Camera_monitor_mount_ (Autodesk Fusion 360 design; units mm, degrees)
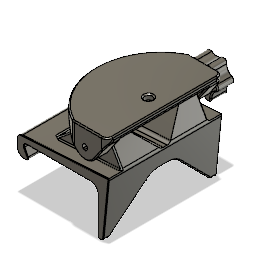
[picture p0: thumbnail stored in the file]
sketch "Sketch1" plane through (0, 0, 0) normal (0, 0, 1) x axis (1, 0, 0)
  line L1 (60, 0) -> (0, 0)
  line L2 (60, 40) -> (60, 0)
  line L3 (0, 40) -> (60, 40)
  line L4 (0, 0) -> (0, 40)
  line L5 (-6, 40) -> (0, 40)
  line L6 (0, 28) -> (-6, 40)
  line L7 (-11, 28) -> (0, 28)
  line L8 (-11, 45) -> (-11, 28)
  line L9 (65, 45) -> (-11, 45)
  line L10 (65, 0) -> (65, 45)
  line L11 (60, 0) -> (65, 0)
  line L12 (65, 0) -> (70, 50)
  line L13 (-11, 45) -> (70, 50)
  line L14 (50, 65) -> (50, 40)
  line L15 (11, 46.358) -> (43.7171, 72.7798)
  line L16 (70, 50) -> (58.6991, 69.9321)
  line L17 (50, 60.6121) -> (46.2, 62.8061)
  line L18 (53.8, 62.8061) -> (50, 60.6121)
  line L19 (53.8, 67.1939) -> (53.8, 62.8061)
  line L20 (50, 69.3879) -> (53.8, 67.1939)
  line L21 (46.2, 67.1939) -> (50, 69.3879)
  line L22 (46.2, 62.8061) -> (46.2, 67.1939)
  line L23 (50, 75.5) -> (50, 65)
  line L24 (25, 75.5) -> (50, 75.5)
  line L25 (43.0004, 57.8582) -> (25, 75.5)
  line L26 (25, 80.5) -> (25, 75.5)
  line L27 (50, 80.5) -> (25, 80.5)
  line L28 (50, 75.5) -> (50, 80.5)
  line L29 (50, 80.5) -> (69.5599, 80.5)
  line L30 (69.5599, 75.5) -> (50, 75.5)
  line L31 (58.1915, 59.2642) -> (69.5599, 75.5)
  line L32 (69.5599, 80.5) -> (69.5599, 75.5)
  line L33 (50, 61.7473) -> (51.6263, 63.3737)
  line L34 (50, 61.7473) -> (48.3737, 63.3737)
  line L35 (49.2, 62.5473) -> (50.8, 62.5473)
  circle C1 centre (50, 65) radius 2.3
  circle C2 centre (50, 65) radius 10
  circle C3 centre (50, 65) radius 15
  circle C4 centre (50, 46) radius 7.5
  point P1 (0, 0)
  point P2 (0, 0)
  point P7 (0, 28)
  point P13 (50, 40)
  point P14 (50, 65)
  point P15 (50, 65)
  point P16 (50, 65)
  point P17 (43.7171, 72.7798)
  point P18 (58.6991, 69.9321)
  point P25 (50, 65)
  point P28 (43.0004, 57.8582)
  point P26 (50, 75.5)
  point P32 (50, 75.5)
  point P30 (50, 80.5)
  point P31 (50, 80.5)
  point P34 (58.1915, 59.2642)
  point P36 (50, 65)
  point P37 (50, 46)
  point P23 (50, 69.3879)
  point P38 (51.6263, 63.3737)
  point P39 (50, 61.7473)
  point P40 (48.3737, 63.3737)
  point P41 (50, 61.7473)
  point P42 (50.8, 62.5473)
  point P43 (49.2, 62.5473)
  point P44 (-11, 45)
  point P45 (-11, 45)
  point P9 (11, 46.358)
  point P3 (60, 0)
  point P5 (0, 40)
  point P6 (-6, 40)
  point P4 (60, 40)
  point P12 (70, 50)
  point P11 (65, 0)
  point P27 (25, 75.5)
  horizontal L1
  vertical L2
  horizontal L3
  vertical L4
  coincident P1 P2
  perpendicular L4 L5
  coincident L4 P7
  perpendicular L4 L7
  perpendicular L7 L8
  perpendicular L8 L9
  perpendicular L9 L10
  perpendicular L2 L11
  coincident L3 P13
  perpendicular L9 L14
  coincident P14 P15
  coincident P14 P16
  coincident C2 P17
  coincident C2 P18
  tangent C2 L16
  tangent C2 L15
  coincident P14 P25
  vertical L23
  perpendicular L23 L24
  coincident C2 P28
  tangent C2 L25
  perpendicular L24 L26
  perpendicular L26 L27
  perpendicular L27 L28
  symmetric P26 L28 P32
  symmetric P30 L28 P31
  coincident C2 P34
  tangent C2 L31
  perpendicular L29 L32
  parallel L27 L29
  parallel L24 L30
  coincident P14 P36
  coincident L14 P37
  coincident P23 L23
  coincident C1 P38
  coincident L14 P39
  tangent C1 L33
  symmetric L14 P38 P40
  symmetric L14 P39 P41
  coincident L33 P42
  coincident L34 P43
  perpendicular L14 L35
  coincident P44 P45
  coincident P9 L13
  dimension "d1" distance P2 P3 = 60
  dimension "d2" distance P2 P5 = 40
  dimension "d3" diameter C1 = 4.6
  dimension "d4" diameter C2 = 20
  dimension "d10" distance P13 P14 = 25
  dimension "d11" distance L5 L9 = 5
  dimension "d13" distance L4 L14 = 50
  dimension "d14" distance L3 P7 = 12
  dimension "d15" distance P5 P6 = 6
  dimension "d16" distance P5 L8 = 11
  dimension "d17" distance P4 P12 = 10
  dimension "d18" distance P4 P12 = 10
  dimension "d19" distance P3 P11 = 5
  dimension "d28" distance P25 L22 = 3.8
  dimension "d51" distance P26 P27 = 25
  dimension "d52" distance P14 P26 = 10.5
  dimension "d54" distance P26 P30 = 5
  dimension "d61" angle L30 L31 = 55
  dimension "d71" diameter C3 = 30
  dimension "d72" diameter C4 = 15
  dimension "d95" angle L14 L33 = 45
  dimension "d96" distance P41 L35 = 0.8
  dimension "d106" distance L9 P37 = 1
  dimension "d107" distance P9 P45 = 22
extrude "Extrude1" new body sketch "Sketch1" profile of L2 L3 L5 L6 L7 L8 L11 L12 L13 along normal blind 100
extrude "Extrude2" add sketch "Sketch1" profile of L13 C1 C2 L15 L16 L17 L18 L19 L20 L21 L22 L25 L31 C3 C4 L33 L34 L35 blind 8 from offset 12
fillet "Fillet1" radius 2
fillet "Fillet2" radius 6
chamfer "Chamfer1" distance 26.2
work_plane "WorkPlane1" AlongDistance 0
split "Split1"
work_plane "WorkPlane2" sketch "Sketch1" AlongDistance 50
extrude "Extrude4" cut sketch "Sketch1" profile of C1 L17 L18 L19 L20 L21 L22 L33 L34 L35 blind 18 from offset 21
extrude "Extrude5" cut sketch "Sketch1" profile of C1 along normal blind 30
mirror "Mirror2"
combine "Combine1"
chamfer "Chamfer5" distance 1
fillet "Fillet5" radius 5
chamfer "Chamfer2" distance 0.5
sketch "Sketch2" plane through (0, 0, 0) normal (1, 0, 0) x axis (0, 0, -1)
  line L1 (-0.5, 0) -> (-99.5, 0)
  line L2 (0, 0) -> (0, 50)
  line L3 (-50, 0) -> (0, 0)
  line L4 (-50, 35) -> (-50, 0)
  line L5 (-5, 0) -> (0, 0)
  line L6 (0, 35) -> (-50, 35)
  line L7 (-40, 35) -> (-5, 0)
  line L8 (-60, 35) -> (-95, 0)
  line L9 (-100, 35) -> (-50, 35)
  line L10 (-50, 0) -> (-100, 0)
  point P1 (0, 0)
  point P6 (0, 0)
  point P7 (-50, 0)
  point P9 (-5, 0)
  point P10 (0, 35)
  point P11 (-40, 35)
  point P16 (-100, 0)
  point P17 (-50, 0)
  point P8 (-50, 35)
  point P14 (-50, 35)
  point P12 (-95, 0)
  point P15 (-100, 35)
  point P13 (-60, 35)
  coincident P1 P6
  midpoint L1 P7
  perpendicular L3 L4
  coincident L1 P9
  parallel L1 L5
  perpendicular L2 L6
  coincident L2 P10
  coincident L6 P11
  symmetric P6 L4 P16
  symmetric P7 L4 P17
  symmetric P8 L4 P14
  symmetric L4 P9 P12
  symmetric L4 P10 P15
  symmetric L4 P11 P13
  dimension "d45" distance P7 P8 = 35
  dimension "d46" angle L3 L7 = 45
  dimension "d47" distance P1 P9 = 5
extrude "Extrude6" cut sketch "Sketch2" profile of L3 L4 L6 L7 L8 L9 L10 along normal blind 80
fillet "Fillet7" radius 15
extrude "Extrude7" new body sketch "Sketch1" profile of C1 C2 L15 L16 L17 L18 L19 L20 L21 L22 L24 L25 L26 L27 L28 L29 L30 L31 L32 C3 L33 L34 L35 along normal blind 11.5
extrude "Extrude8" add sketch "Sketch1" profile of L24 L26 L27 L28 L29 L30 L32 C3 along normal blind 50
extrude "Extrude14" add of existing geometry blind 1
mirror "Mirror3"
combine "Combine2"
extrude "Extrude9" add of existing geometry blind 30
sketch "Sketch3" plane through (0, 0, 0) normal (0, 1, 0) x axis (1, 0, 0)
  line L1 (55, 0) -> (0, 0)
  line L2 (55, -50) -> (55, 0)
  line L3 (0, -50) -> (55, -50)
  line L4 (0, 0) -> (0, -50)
  line L5 (55, -50) -> (74.9186, -38.5)
  circle C1 centre (66, -50) radius 57.5
  circle C2 centre (55, -50) radius 3.5
  circle C3 centre (55, -27) radius 14
  circle C4 centre (55, -50) radius 37
  circle C5 centre (55, -50) radius 9
  circle C6 centre (74.9186, -38.5) radius 14
  point P1 (0, 0)
  point P2 (0, 0)
  point P4 (55, -50)
  point P7 (55, -50)
  point P11 (74.9186, -38.5)
  point P12 (74.9186, -38.5)
  point P8 (55, -27)
  point P3 (55, 0)
  point P5 (0, -50)
  point P6 (66, -50)
  point P10 (55, -50)
  horizontal L1
  vertical L2
  horizontal L3
  vertical L4
  coincident P1 P2
  coincident P4 P7
  concentric C2 C4
  tangent C3 C4
  concentric C4 C5
  tangent C3 C5
  tangent C4 C6
  tangent C5 C6
  coincident P11 P12
  coincident L2 P8
  dimension "d64" distance P2 P3 = 55
  dimension "d65" distance P2 P5 = 50
  dimension "d66" diameter C1 = 115
  dimension "d70" diameter C2 = 7
  dimension "d97" distance P6 P7 = 11
  dimension "d98" diameter C3 = 28
  dimension "d100" distance P8 P10 = 23
  dimension "d102" angle L2 L5 = 60
extrude "Extrude10" sketch "Sketch3" profile of C1 C2 C3 C4 C5 C6 along normal blind 80
fillet "Fillet9" radius 5
chamfer "Chamfer3" distance 1
chamfer "Chamfer8" distance 1
extrude "Extrude11" new body sketch "Sketch1" profile of L13 C1 C2 L15 L16 L17 L18 L19 L20 L21 L22 L24 L25 L28 L30 L31 C3 C4 blind -15 from offset -1
extrude "Extrude12" cut sketch "Sketch1" profile of C3 C4 against normal blind 16
circular_pattern "C-Pattern1" TotalAngle 360
extrude "Extrude13" cut sketch "Sketch1" profile of C1 L17 L18 L19 L20 L21 L22 blind -10 from offset -9
fillet "Fillet10" radius 3
chamfer "Chamfer6" distance 1
chamfer "Chamfer7" distance 1.6
move "Move1"
move "Move2"
move "Move3"
move "Move4" RotateAngle -90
